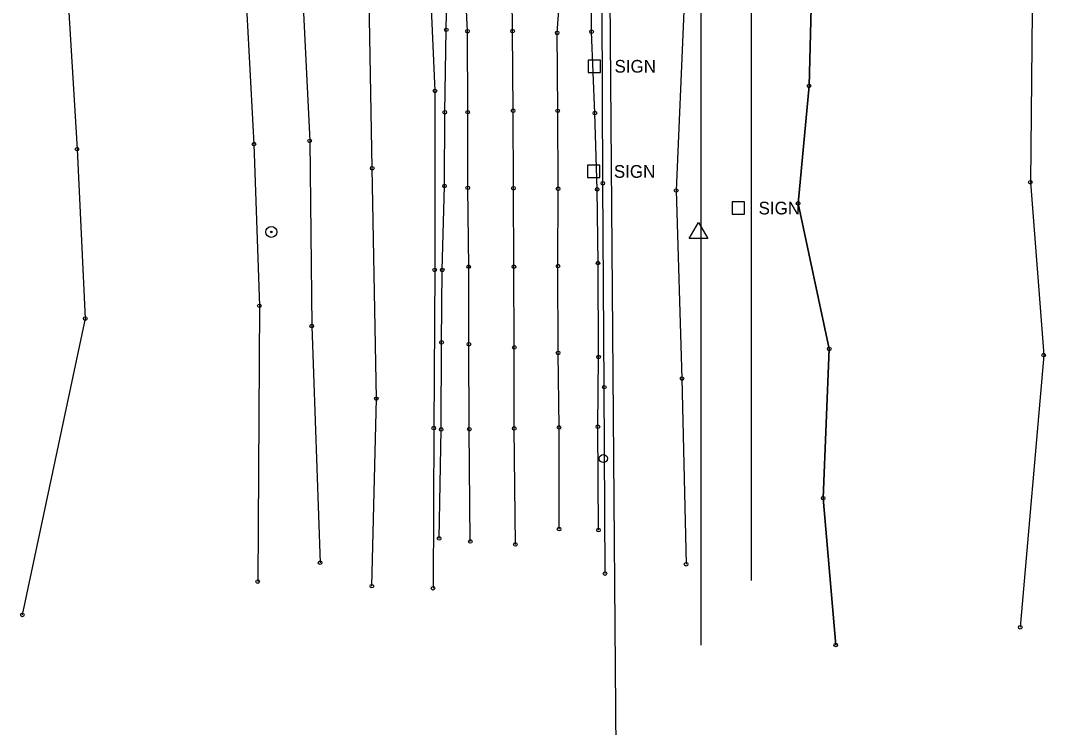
# Model space of a CAD drawing. Extents: x 23349949 to 23380641, y 6790552 to 6802878.
# Drawn here: x 23379696.5 to 23379979.4, y 6801455.6 to 6801650.8 of the extents above; entities that cross this region are included whole.
import ezdxf

# ---------------------------------------------------------------- set-up
doc = ezdxf.new("R2010")
doc.units = 0
for name, color, linetype in [('Default', 7, 'Continuous'), ('EXT_BL', 7, 'Continuous'), ('EXT_C', 7, 'Continuous'), ('EXT_D', 7, 'Continuous'), ('EXT_EP', 7, 'Continuous'), ('EXT_SH', 7, 'Continuous'), ('Natural', 7, 'Continuous'), ('Section Lines', 7, 'Continuous'), ('SurControl', 7, 'Continuous'), ('SurPointsNonDTM', 7, 'Continuous'), ('SurRoadPoints', 7, 'Continuous'), ('SurSurveyPoints', 7, 'Continuous'), ('UtilitiesBelowGround', 7, 'Continuous')]:
    doc.layers.add(name, color=color, linetype=linetype)

msp = doc.modelspace()

# ---------------------------------------------------------------- linework, layer by layer
at = {"layer": 'Default'}
msp.add_line((23379765.76, 6801592.39), (23379765.76, 6801592.39), dxfattribs=at)
at = {"layer": 'EXT_BL'}
for points in [[(23379703.1, 6801920.29), (23379702.18, 6801870.03), (23379709, 6801818.22), (23379709.48, 6801768.84), (23379709.92, 6801712.49), (23379709.34, 6801662.19), (23379712.14, 6801615.26), (23379714.4, 6801568.49), (23379697.04, 6801486.66)], [(23379746.93, 6801861.44), (23379757.46, 6801839.17), (23379757.68, 6801821.63), (23379757.83, 6801766.85), (23379758.62, 6801712.77), (23379758.42, 6801663.1), (23379760.97, 6801616.65), (23379762.46, 6801572), (23379761.99, 6801495.88)], [(23379811.86, 6801814.96), (23379803.64, 6801808.04), (23379771.83, 6801781.7), (23379772.35, 6801765.01), (23379771.47, 6801714.18), (23379771.48, 6801714.19), (23379773.88, 6801667.84), (23379776.35, 6801617.55), (23379776.91, 6801566.43), (23379779.21, 6801501.08)], [(23379877.6, 6801797.12), (23379883.73, 6801754.07), (23379881.76, 6801705.27), (23379879.61, 6801653.36), (23379877.45, 6801603.84), (23379879.08, 6801551.92), (23379880.22, 6801500.65)], [(23379921.53, 6801478.35), (23379918.04, 6801518.9), (23379919.73, 6801560.1), (23379911.12, 6801600.29), (23379914.15, 6801632.72), (23379915.42, 6801679.56), (23379903.91, 6801718.73), (23379905.76, 6801758.12), (23379912.41, 6801791.06)], [(23379961.65, 6801790.54), (23379968.85, 6801761.01), (23379970.88, 6801710.89), (23379975.83, 6801662.84), (23379975.22, 6801606.12), (23379978.9, 6801558.4), (23379972.43, 6801483.26)], [(23379857.85, 6801498.08), (23379857.65, 6801549.54), (23379857.24, 6801605.84), (23379857.08, 6801654.63), (23379855.9, 6801712.41), (23379854.7, 6801764.68), (23379851.87, 6801780.05), (23379848.61, 6801783.39), (23379848.48, 6801782.12), (23379847.85, 6801782.14)], [(23379811.82, 6801779.98), (23379812.16, 6801746.8), (23379808.74, 6801700.4), (23379809.1, 6801670.71), (23379810.92, 6801631.35), (23379810.84, 6801581.92), (23379810.59, 6801538.25), (23379810.38, 6801494.02)]]:
    msp.add_lwpolyline(points, dxfattribs=at)
at = {"layer": 'EXT_C'}
msp.add_lwpolyline([(23379833.11, 6801506.12), (23379832.79, 6801538.15), (23379832.81, 6801560.52), (23379832.69, 6801582.8), (23379832.58, 6801604.47), (23379832.48, 6801625.87), (23379832.33, 6801647.85), (23379832.25, 6801657.38), (23379832.21, 6801667.3), (23379832.28, 6801677.12), (23379832.35, 6801698.29), (23379832.11, 6801718.47), (23379832.17, 6801741.62), (23379831.95, 6801766.64), (23379831.84, 6801774.96), (23379831.81, 6801786.36)], dxfattribs=at)
at = {"layer": 'EXT_D'}
msp.add_line((23379898.3, 6801496.16), (23379898.3, 6801699.04), dxfattribs=at)
msp.add_lwpolyline([(23379793.51, 6801494.6), (23379794.74, 6801546.37), (23379793.6, 6801609.98), (23379790.63, 6801775.37), (23379806.04, 6801824.96)], dxfattribs=at)
at = {"layer": 'EXT_EP'}
for points in [[(23379820.67, 6801506.94), (23379820.4, 6801537.92), (23379820.29, 6801561.41), (23379820.22, 6801582.8), (23379819.98, 6801604.58), (23379819.95, 6801625.47), (23379819.9, 6801647.82), (23379819.42, 6801657.42), (23379819.18, 6801667.32), (23379819.26, 6801677.25), (23379819.77, 6801698.03), (23379819.68, 6801719.01), (23379819.66, 6801741.23), (23379819.61, 6801766.55), (23379819.6, 6801775), (23379819.6, 6801786.29)], [(23379845.18, 6801510.36), (23379845.15, 6801538.43), (23379844.89, 6801559.01), (23379844.87, 6801582.96), (23379844.91, 6801604.33), (23379844.79, 6801625.84), (23379844.64, 6801647.35), (23379845.34, 6801657.48), (23379845.21, 6801667.16), (23379845.34, 6801677.56), (23379844.69, 6801698.54), (23379844.48, 6801717.68), (23379844.52, 6801741.69), (23379844.29, 6801766.73), (23379844.29, 6801774.92), (23379844.29, 6801786.32)]]:
    msp.add_lwpolyline(points, dxfattribs=at)
at = {"layer": 'EXT_SH'}
for points in [[(23379812.05, 6801507.78), (23379812.63, 6801537.87), (23379812.74, 6801561.9), (23379812.93, 6801581.9), (23379813.55, 6801605.08), (23379813.63, 6801625.46), (23379814.05, 6801648.21), (23379814.16, 6801657.62), (23379814.31, 6801667.59), (23379814.43, 6801677.38), (23379814.68, 6801698.14), (23379816.59, 6801719.65), (23379817.67, 6801741.52), (23379817.1, 6801766.53), (23379817.1, 6801766.53), (23379817.11, 6801775.01), (23379816.92, 6801786.27)], [(23379856.05, 6801510.07), (23379855.87, 6801538.6), (23379856.07, 6801557.88), (23379855.92, 6801583.82), (23379855.68, 6801604.16), (23379855.06, 6801625.22), (23379854.13, 6801647.68), (23379854.07, 6801656.07), (23379853.02, 6801671.41), (23379852.3, 6801678.32), (23379850.44, 6801698.27), (23379848.4, 6801718.65), (23379846.94, 6801741.66), (23379847, 6801766.75), (23379846.85, 6801774.91), (23379846.83, 6801786.31)]]:
    msp.add_lwpolyline(points, dxfattribs=at)
at = {"layer": 'Natural'}
msp.add_lwpolyline([(23379912.41, 6801791.06), (23379905.76, 6801758.12), (23379903.91, 6801718.73), (23379915.42, 6801679.56), (23379914.15, 6801632.72), (23379911.12, 6801600.29), (23379919.73, 6801560.1), (23379918.04, 6801518.9), (23379921.53, 6801478.35)], dxfattribs=at)
at = {"layer": 'Section Lines'}
msp.add_line((23379862.42, 6801260.03), (23379853.19, 6802427.68), dxfattribs=at)
at = {"layer": 'SurControl'}
msp.add_lwpolyline([(23379883.66, 6801595.01), (23379886.21, 6801590.6), (23379881.11, 6801590.6)], close=True, dxfattribs=at)
msp.add_circle((23379857.38, 6801529.83), 1.12, dxfattribs=at)
at = {"layer": 'SurPointsNonDTM'}
for centre in [(23379914.15, 6801632.72), (23379911.12, 6801600.29), (23379919.73, 6801560.1), (23379918.04, 6801518.9), (23379921.53, 6801478.35)]:
    msp.add_circle(centre, 0.5, dxfattribs=at)
at = {"layer": 'SurRoadPoints'}
for points in [[(23379854.86, 6801636.43), (23379854.86, 6801636.43), (23379856.58, 6801636.43), (23379856.58, 6801639.85), (23379853.15, 6801639.85), (23379853.15, 6801636.43), (23379854.86, 6801636.43)], [(23379854.69, 6801607.39), (23379854.69, 6801607.39), (23379856.4, 6801607.39), (23379856.4, 6801610.82), (23379852.97, 6801610.82), (23379852.97, 6801607.39), (23379854.69, 6801607.39)], [(23379894.62, 6801597.28), (23379894.62, 6801597.28), (23379896.33, 6801597.28), (23379896.33, 6801600.71), (23379892.91, 6801600.71), (23379892.91, 6801597.28), (23379894.62, 6801597.28)]]:
    msp.add_lwpolyline(points, dxfattribs=at)
for radius in [1.5, 0.25]:
    msp.add_circle((23379765.76, 6801592.39), radius, dxfattribs=at)
at = {"layer": 'SurSurveyPoints'}
for centre in [(23379814.05, 6801648.21), (23379819.9, 6801647.82), (23379832.33, 6801647.85), (23379844.64, 6801647.35), (23379854.13, 6801647.68), (23379914.15, 6801632.72), (23379810.92, 6801631.35), (23379813.63, 6801625.46), (23379819.95, 6801625.47), (23379832.48, 6801625.87), (23379844.79, 6801625.84), (23379855.06, 6801625.22), (23379776.35, 6801617.55), (23379712.14, 6801615.26), (23379760.97, 6801616.65), (23379793.6, 6801609.98), (23379813.55, 6801605.08), (23379819.98, 6801604.58), (23379832.58, 6801604.47), (23379844.91, 6801604.33), (23379855.68, 6801604.16), (23379857.24, 6801605.84), (23379877.45, 6801603.84), (23379975.22, 6801606.12), (23379911.12, 6801600.29), (23379855.92, 6801583.82), (23379810.84, 6801581.92), (23379812.93, 6801581.9), (23379820.22, 6801582.8), (23379832.69, 6801582.8), (23379844.87, 6801582.96), (23379762.46, 6801572), (23379714.4, 6801568.49), (23379776.91, 6801566.43), (23379812.74, 6801561.9), (23379820.29, 6801561.41), (23379832.81, 6801560.52), (23379844.89, 6801559.01), (23379919.73, 6801560.1), (23379978.9, 6801558.4), (23379856.07, 6801557.88), (23379879.08, 6801551.92), (23379857.65, 6801549.54), (23379794.74, 6801546.37), (23379845.15, 6801538.43), (23379855.87, 6801538.6), (23379810.59, 6801538.25), (23379812.63, 6801537.87), (23379820.4, 6801537.92), (23379832.79, 6801538.15), (23379918.04, 6801518.9), (23379845.18, 6801510.36), (23379856.05, 6801510.07), (23379812.05, 6801507.78), (23379820.67, 6801506.94), (23379833.11, 6801506.12), (23379779.21, 6801501.08), (23379880.22, 6801500.65), (23379857.85, 6801498.08), (23379761.99, 6801495.88), (23379793.51, 6801494.6), (23379810.38, 6801494.02), (23379697.04, 6801486.66), (23379972.43, 6801483.26), (23379921.53, 6801478.35)]:
    msp.add_circle(centre, 0.5, dxfattribs=at)
at = {"layer": 'UtilitiesBelowGround'}
for p, q in [((23379884.41, 6801592.39), (23379884.28, 6801871.88)), ((23379884.41, 6801478.35), (23379884.41, 6801592.39))]:
    msp.add_line(p, q, dxfattribs=at)

# ---------------------------------------------------------------- texts
at = {"layer": 'SurRoadPoints'}
for p in [(23379860.47, 6801636.39), (23379860.29, 6801607.36), (23379900.23, 6801597.24)]:
    msp.add_text('SIGN', height=3.498, dxfattribs=at).set_placement(p)

doc.saveas('drawing.dxf')
